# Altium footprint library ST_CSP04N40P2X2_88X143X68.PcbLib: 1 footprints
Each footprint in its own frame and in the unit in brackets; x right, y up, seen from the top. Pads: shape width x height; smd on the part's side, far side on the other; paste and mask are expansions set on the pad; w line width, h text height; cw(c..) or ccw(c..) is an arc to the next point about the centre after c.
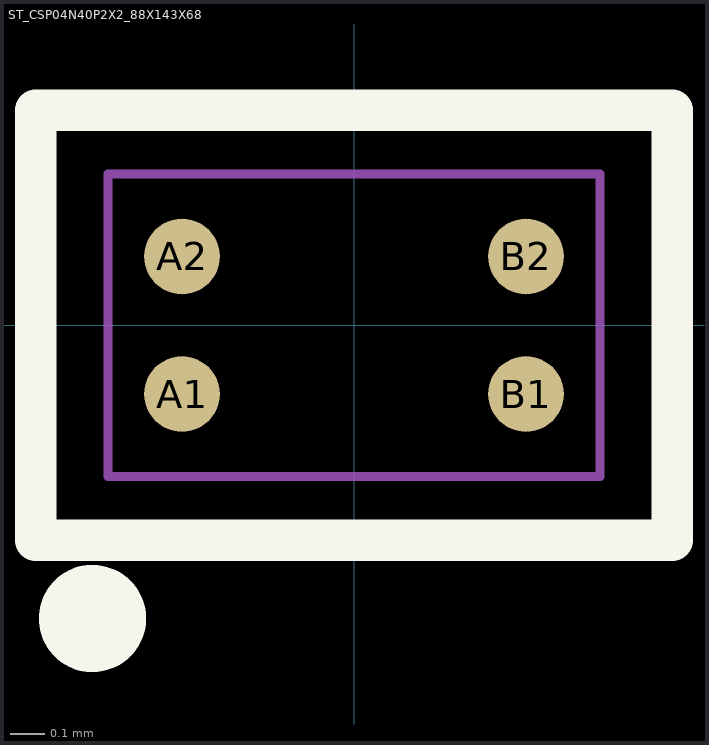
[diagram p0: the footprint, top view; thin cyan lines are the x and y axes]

## ST_CSP04N40P2X2_88X143X68 [mm] "ST_CSP04N40P2X2_88X143X68"
pads (4):
  round 0.22 smd mask+0.05: A1(-0.5,-0.2) A2(-0.5,0.2) B1(0.5,-0.2) B2(0.5,0.2)
Top Overlay:
  circle w0.2: c-0.76,-0.852 r0.056
  lines w0.12: -0.925,-0.625 -0.925,0.625 0.925,0.625 0.925,-0.625 -0.925,-0.625
Top Paste:
  rectangle: 0.39,-0.31 0.61,-0.09
  rectangle: 0.39,0.09 0.61,0.31
  rectangle: -0.61,0.09 -0.39,0.31
  rectangle: -0.61,-0.31 -0.39,-0.09
Mechanical 5:
  text "A1" at -0.547,0.03 h0.07
  text "A2" at -0.542,0.36 h0.07
  text "B2" at 0.443,0.38 h0.07
  text "B1" at 0.448,-0.03 h0.07
Mechanical 6:
  lines w0.025: -0.715,-0.44 0.715,-0.44 0.715,0.44 -0.715,0.44 -0.715,-0.44
Mechanical 7:
  lines w0.025: -0.715,-0.44 -0.715,0.44 0.715,0.44 0.715,-0.44 -0.715,-0.44
3D body: height 0.68, standoff 0.18, extent -0.715,-0.44 0.715,0.44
